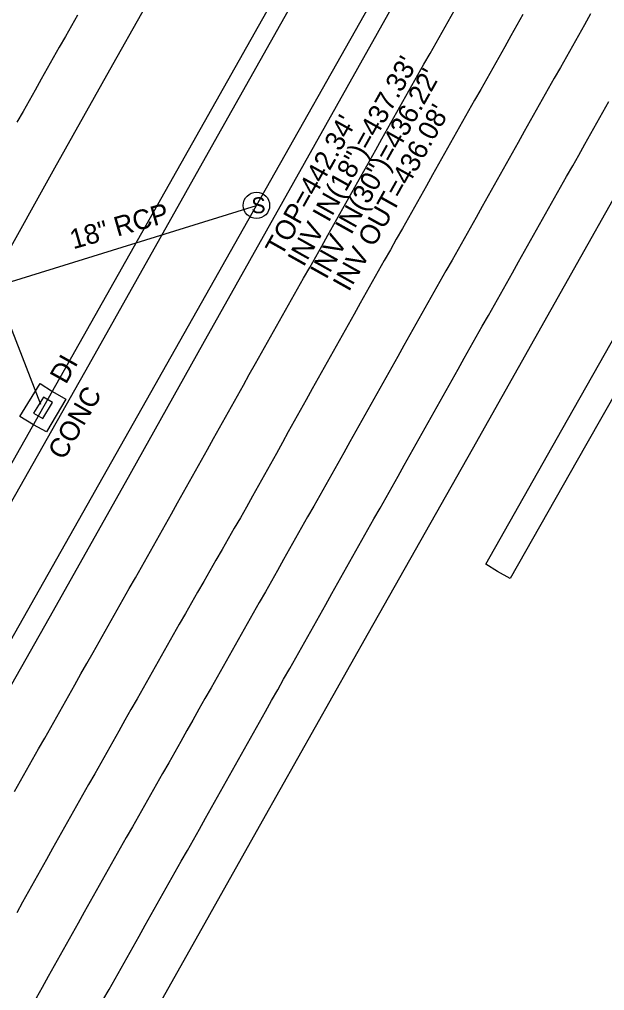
# Model space of a CAD drawing. Extents: x 2074109 to 2077820, y 741079 to 746031.
# Drawn here: x 2075216 to 2075335.2, y 742680.2 to 742877.9 of the extents above; entities that cross this region are included whole.
import ezdxf

# ---------------------------------------------------------------- set-up
doc = ezdxf.new("R2010")
doc.units = 0
for name, color, linetype in [('Exist Guardrail Cable Guide Rail', 7, 'Continuous'), ('Exist Horizontal Alignment', 7, 'Continuous'), ('Exist Roads EOP', 7, 'Continuous'), ('Exist Roads EOT', 7, 'Continuous'), ('Exist Structure Minor Drop Inlet', 7, 'Continuous'), ('Exist Structure Minor Drop Inlet Text', 7, 'Continuous'), ('Exist Structure Minor Paved Ditch or Gutter', 7, 'Continuous'), ('Exist Structure Minor Paved Ditch or Gutter Text', 7, 'Continuous'), ('Exist Structure Minor Pipes RCP 18 Inch', 7, 'Continuous'), ('Exist Structure Minor Pipes RCP 18 Inch Text', 7, 'Continuous'), ('Exist Structure Minor Pipes RCP 24 Inch Invert', 7, 'Continuous'), ('Exist Structure Minor Pipes RCP 30 Inch', 7, 'Continuous'), ('Exist Structure Minor Pipes RCP 30 Inch Invert', 7, 'Continuous'), ('Exist Structure Minor Storm Sewer Manhole CELL', 7, 'Continuous'), ('Exist Structure Minor Storm Sewer Manhole Text', 7, 'Continuous')]:
    doc.layers.add(name, color=color, linetype=linetype)

msp = doc.modelspace()

# ---------------------------------------------------------------- linework, layer by layer
at = {"layer": 'Exist Guardrail Cable Guide Rail'}
msp.add_line((2075230.21, 742807.65), (2075255.1, 742852.02), dxfattribs=at)
for points in [[(2075255.1, 742852.02), (2075298.94, 742929.85), (2075345.78, 743013.07), (2075384.51, 743080.82), (2075424.32, 743152.8), (2075460.45, 743220.68)], [(2075043.78, 742487.09), (2075058.56, 742508.52), (2075082.64, 742547.78), (2075110.14, 742595.62), (2075138.25, 742645.19), (2075162.9, 742688.2), (2075192.42, 742740.98), (2075230.21, 742807.65)]]:
    msp.add_lwpolyline(points, dxfattribs=at)
at = {"layer": 'Exist Horizontal Alignment'}
msp.add_line((2074886.11, 742205.34), (2075575.25, 743427.42), dxfattribs=at)
at = {"layer": 'Exist Roads EOP'}
for points in [[(2075082.27, 742583.2), (2075090.46, 742602.42), (2075097.51, 742619.27), (2075103.18, 742632.87), (2075107.04, 742641.29), (2075110.49, 742647.54), (2075117.02, 742659.24), (2075126.42, 742676.04), (2075137.8, 742696.19), (2075150.38, 742718.4), (2075162.39, 742739.69), (2075174.19, 742760.67), (2075186.87, 742783.1), (2075199.9, 742806.12), (2075211.88, 742827.44), (2075223.21, 742847.7), (2075235.01, 742868.73), (2075246.83, 742889.73)], [(2075297.48, 742890.45), (2075284.83, 742867.93), (2075269.65, 742840.85), (2075253.28, 742811.72), (2075237.58, 742783.58), (2075222.02, 742755.92), (2075207.65, 742730.63), (2075195.18, 742708.56), (2075181.14, 742683.69), (2075166.05, 742656.95), (2075153.79, 742635.53), (2075144.79, 742622.27), (2075137.94, 742612.64), (2075128.78, 742600.5), (2075119.38, 742587.81), (2075112.7, 742578.93), (2075100.64, 742561.46), (2075086.67, 742540.76)], [(2075349.99, 742864.53), (2075330.27, 742829.51), (2075308.21, 742790.39), (2075287.02, 742752.93), (2075265.47, 742714.71), (2075243.99, 742676.52)]]:
    msp.add_lwpolyline(points, dxfattribs=at)
at = {"layer": 'Exist Roads EOT'}
for points in [[(2075215.02, 742720.7), (2075216.25, 742722.88), (2075217.48, 742725.06), (2075218.71, 742727.24), (2075219.93, 742729.41), (2075221.16, 742731.59), (2075222.39, 742733.77), (2075223.62, 742735.94), (2075224.85, 742738.12), (2075226.08, 742740.3), (2075227.31, 742742.47), (2075228.54, 742744.65), (2075229.77, 742746.82), (2075231, 742749), (2075232.23, 742751.17), (2075233.46, 742753.35), (2075234.69, 742755.53), (2075235.92, 742757.7), (2075237.16, 742759.88), (2075238.39, 742762.05), (2075239.62, 742764.23), (2075240.85, 742766.41), (2075242.08, 742768.58), (2075243.31, 742770.76), (2075244.54, 742772.93), (2075245.77, 742775.11), (2075247, 742777.29), (2075248.22, 742779.47), (2075249.44, 742781.65), (2075250.65, 742783.83), (2075251.87, 742786.02), (2075253.09, 742788.2), (2075254.31, 742790.38), (2075255.53, 742792.57), (2075256.74, 742794.75), (2075257.96, 742796.93), (2075259.18, 742799.11), (2075260.4, 742801.3), (2075261.62, 742803.48), (2075262.83, 742805.66), (2075264.06, 742807.84), (2075265.29, 742810.02), (2075266.52, 742812.19), (2075267.75, 742814.37), (2075268.98, 742816.55), (2075270.2, 742818.73), (2075271.43, 742820.9), (2075272.66, 742823.08), (2075273.89, 742825.26), (2075275.12, 742827.43), (2075276.35, 742829.61), (2075277.57, 742831.79), (2075278.8, 742833.97), (2075280.03, 742836.15), (2075281.25, 742838.33), (2075282.47, 742840.51), (2075283.69, 742842.69), (2075284.92, 742844.87), (2075286.14, 742847.05), (2075287.36, 742849.23), (2075288.58, 742851.41), (2075289.81, 742853.59), (2075291.03, 742855.77), (2075292.25, 742857.95), (2075293.47, 742860.13), (2075294.7, 742862.31), (2075295.93, 742864.48), (2075297.16, 742866.66), (2075298.39, 742868.83), (2075299.62, 742871.01), (2075300.86, 742873.18), (2075302.09, 742875.36), (2075303.32, 742877.54), (2075304.55, 742879.71)], [(2075318.55, 742878.91), (2075317.32, 742876.74), (2075316.09, 742874.56), (2075314.86, 742872.38), (2075313.63, 742870.21), (2075312.4, 742868.03), (2075311.17, 742865.86), (2075309.94, 742863.68), (2075308.71, 742861.51), (2075307.48, 742859.33), (2075306.25, 742857.15), (2075305.02, 742854.97), (2075303.8, 742852.79), (2075302.58, 742850.61), (2075301.35, 742848.43), (2075300.13, 742846.26), (2075298.9, 742844.08), (2075297.67, 742841.9), (2075296.44, 742839.72), (2075295.22, 742837.55), (2075293.99, 742835.37), (2075292.76, 742833.19), (2075291.54, 742831.01), (2075290.31, 742828.83), (2075289.08, 742826.66), (2075287.85, 742824.48), (2075286.63, 742822.3), (2075285.4, 742820.13), (2075284.17, 742817.95), (2075282.94, 742815.77), (2075281.71, 742813.59), (2075280.5, 742811.41), (2075279.28, 742809.23), (2075278.06, 742807.04), (2075276.85, 742804.86), (2075275.63, 742802.68), (2075274.41, 742800.49), (2075273.2, 742798.31), (2075271.98, 742796.12), (2075270.76, 742793.94), (2075269.55, 742791.76), (2075268.33, 742789.57), (2075267.11, 742787.39), (2075265.9, 742785.2), (2075264.69, 742783.02), (2075263.47, 742780.83), (2075262.26, 742778.65), (2075261.02, 742776.48), (2075259.77, 742774.31), (2075258.53, 742772.14), (2075257.28, 742769.98), (2075256.03, 742767.81), (2075254.79, 742765.64), (2075253.54, 742763.48), (2075252.29, 742761.31), (2075251.05, 742759.14), (2075249.8, 742756.98), (2075248.56, 742754.81), (2075247.31, 742752.64), (2075246.08, 742750.47), (2075244.86, 742748.29), (2075243.64, 742746.1), (2075242.42, 742743.92), (2075241.19, 742741.75), (2075239.96, 742739.57), (2075238.73, 742737.39), (2075237.49, 742735.22), (2075236.26, 742733.04), (2075235.03, 742730.87), (2075233.8, 742728.69), (2075232.57, 742726.52), (2075231.34, 742724.34), (2075230.11, 742722.17), (2075228.88, 742719.99), (2075227.65, 742717.81), (2075226.42, 742715.64), (2075225.2, 742713.46), (2075223.97, 742711.28), (2075222.75, 742709.1), (2075221.53, 742706.91), (2075220.32, 742704.73), (2075219.1, 742702.55), (2075217.89, 742700.36), (2075216.67, 742698.18), (2075215.46, 742695.99)], [(2075227.84, 742878.78), (2075226.6, 742876.61), (2075225.37, 742874.44), (2075224.13, 742872.26), (2075222.9, 742870.09), (2075221.67, 742867.91), (2075220.44, 742865.74), (2075219.21, 742863.56), (2075217.98, 742861.38), (2075216.75, 742859.21), (2075215.52, 742857.03)], [(2075332.29, 742879.04), (2075331.06, 742876.86), (2075329.84, 742874.68), (2075328.61, 742872.5), (2075327.38, 742870.32), (2075326.16, 742868.15), (2075324.93, 742865.97), (2075323.7, 742863.79), (2075322.47, 742861.61), (2075321.25, 742859.44), (2075320.02, 742857.26), (2075318.79, 742855.08), (2075317.57, 742852.9), (2075316.34, 742850.72), (2075315.13, 742848.54), (2075313.92, 742846.35), (2075312.71, 742844.16), (2075311.49, 742841.98), (2075310.25, 742839.81), (2075309.02, 742837.63), (2075307.79, 742835.46), (2075306.56, 742833.28), (2075305.33, 742831.11), (2075304.1, 742828.93), (2075302.86, 742826.76), (2075301.63, 742824.58), (2075300.4, 742822.41), (2075299.17, 742820.23), (2075297.94, 742818.06), (2075296.71, 742815.88), (2075295.49, 742813.7), (2075294.27, 742811.51), (2075293.05, 742809.33), (2075291.84, 742807.15), (2075290.61, 742804.97), (2075289.39, 742802.79), (2075288.17, 742800.61), (2075286.94, 742798.43), (2075285.72, 742796.25), (2075284.5, 742794.07), (2075283.27, 742791.89), (2075282.05, 742789.71), (2075280.83, 742787.53), (2075279.61, 742785.35), (2075278.38, 742783.17), (2075277.16, 742780.99), (2075275.93, 742778.81), (2075274.7, 742776.63), (2075273.47, 742774.46), (2075272.24, 742772.28), (2075271.01, 742770.11), (2075269.78, 742767.93), (2075268.55, 742765.75), (2075267.32, 742763.58), (2075266.09, 742761.4), (2075264.86, 742759.22), (2075263.63, 742757.05), (2075262.4, 742754.87), (2075261.18, 742752.69), (2075259.95, 742750.52), (2075258.72, 742748.34), (2075257.49, 742746.16), (2075256.26, 742743.99), (2075255.03, 742741.81), (2075253.8, 742739.63), (2075252.57, 742737.46), (2075251.34, 742735.28), (2075250.11, 742733.11), (2075248.88, 742730.93), (2075247.64, 742728.76), (2075246.41, 742726.58), (2075245.18, 742724.41), (2075243.94, 742722.23), (2075242.71, 742720.06), (2075241.48, 742717.88), (2075240.25, 742715.71), (2075239.01, 742713.54), (2075237.78, 742711.36), (2075236.55, 742709.19), (2075235.32, 742707.01), (2075234.09, 742704.84), (2075232.86, 742702.66), (2075231.63, 742700.48), (2075230.41, 742698.3), (2075229.19, 742696.12), (2075227.97, 742693.93), (2075226.75, 742691.75), (2075225.53, 742689.57), (2075224.31, 742687.39), (2075223.09, 742685.21), (2075221.87, 742683.03), (2075220.65, 742680.84), (2075219.43, 742678.66)], [(2075233.03, 742678.23), (2075234.26, 742680.41), (2075235.49, 742682.59), (2075236.71, 742684.76), (2075237.94, 742686.94), (2075239.17, 742689.12), (2075240.39, 742691.3), (2075241.62, 742693.48), (2075242.85, 742695.65), (2075244.07, 742697.83), (2075245.3, 742700.01), (2075246.53, 742702.19), (2075247.75, 742704.37), (2075248.98, 742706.54), (2075250.21, 742708.72), (2075251.43, 742710.9), (2075252.66, 742713.08), (2075253.89, 742715.26), (2075255.11, 742717.44), (2075256.34, 742719.61), (2075257.57, 742721.79), (2075258.79, 742723.97), (2075260.02, 742726.15), (2075261.24, 742728.33), (2075262.47, 742730.5), (2075263.7, 742732.68), (2075264.92, 742734.86), (2075266.15, 742737.04), (2075267.37, 742739.22), (2075268.6, 742741.4), (2075269.82, 742743.58), (2075271.05, 742745.76), (2075272.27, 742747.93), (2075273.5, 742750.11), (2075274.72, 742752.29), (2075275.95, 742754.47), (2075277.17, 742756.65), (2075278.4, 742758.83), (2075279.62, 742761.01), (2075280.85, 742763.19), (2075282.08, 742765.36), (2075283.3, 742767.54), (2075284.53, 742769.72), (2075285.76, 742771.9), (2075286.98, 742774.08), (2075288.21, 742776.25), (2075289.44, 742778.43), (2075290.67, 742780.61), (2075291.89, 742782.79), (2075293.12, 742784.96), (2075294.35, 742787.14), (2075295.57, 742789.32), (2075296.8, 742791.5), (2075298.03, 742793.68), (2075299.25, 742795.86), (2075300.48, 742798.04), (2075301.7, 742800.21), (2075302.93, 742802.39), (2075304.15, 742804.57), (2075305.37, 742806.75), (2075306.6, 742808.93), (2075307.82, 742811.11), (2075309.05, 742813.29), (2075310.27, 742815.47), (2075311.5, 742817.65), (2075312.72, 742819.83), (2075313.95, 742822), (2075315.18, 742824.18), (2075316.4, 742826.36), (2075317.63, 742828.54), (2075318.86, 742830.72), (2075320.08, 742832.89), (2075321.31, 742835.07), (2075322.54, 742837.25), (2075323.76, 742839.43), (2075324.99, 742841.61), (2075326.22, 742843.78), (2075327.44, 742845.96), (2075328.67, 742848.14), (2075329.9, 742850.32), (2075331.12, 742852.5), (2075332.35, 742854.67), (2075333.58, 742856.85), (2075334.81, 742859.03), (2075336.03, 742861.21)]]:
    msp.add_lwpolyline(points, dxfattribs=at)
at = {"layer": 'Exist Structure Minor Drop Inlet'}
msp.add_lwpolyline([(2075220.89, 742801.04), (2075218.9, 742797.78), (2075220.77, 742796.65), (2075222.75, 742799.9)], close=True, dxfattribs=at)
at = {"layer": 'Exist Structure Minor Paved Ditch or Gutter'}
for points in [[(2075381.77, 742879.44), (2075355.36, 742833.4), (2075331.29, 742791.11), (2075315.93, 742764.1), (2075313.38, 742765.52), (2075310.97, 742766.98), (2075326.43, 742794.39), (2075350.27, 742836.4), (2075376.88, 742883)], [(2075220.23, 742803.78), (2075222.73, 742802.18), (2075225.49, 742800.61), (2075221.53, 742793.94), (2075218.87, 742795.39), (2075216.1, 742797.05), (2075220.23, 742803.78)]]:
    msp.add_lwpolyline(points, dxfattribs=at)
at = {"layer": 'Exist Structure Minor Pipes RCP 18 Inch'}
for p, q in [((2075212.46, 742823.93), (2075264.27, 742840.07)), ((2075211.47, 742822.3), (2075220.31, 742799.59))]:
    msp.add_line(p, q, dxfattribs=at)
at = {"layer": 'Exist Structure Minor Pipes RCP 30 Inch'}
for p, q in [((2075264.27, 742840.07), (2075435.52, 743142.56)), ((2074933.64, 742254.78), (2075264.27, 742840.07))]:
    msp.add_line(p, q, dxfattribs=at)
at = {"layer": 'Exist Structure Minor Storm Sewer Manhole CELL'}
msp.add_circle((2075264.27, 742840.07), 2.69, dxfattribs=at)

# ---------------------------------------------------------------- texts
at = {"layer": 'Exist Structure Minor Drop Inlet Text'}
msp.add_text('DI', height=4, rotation=60.7411, dxfattribs=at).set_placement((2075225.49, 742803.47))
at = {"layer": 'Exist Structure Minor Paved Ditch or Gutter Text'}
msp.add_text('CONC', height=4, rotation=60.1413, dxfattribs=at).set_placement((2075225.07, 742788.01))
at = {"layer": 'Exist Structure Minor Pipes RCP 18 Inch Text'}
msp.add_text('18" RCP', height=4, rotation=15.9959, dxfattribs=at).set_placement((2075226.97, 742831.11))
at = {"layer": 'Exist Structure Minor Pipes RCP 24 Inch Invert'}
msp.add_text('INV IN(18")=437.33\'', height=4, rotation=60.7411, dxfattribs=at).set_placement((2075273.89, 742827.37))
at = {"layer": 'Exist Structure Minor Pipes RCP 30 Inch Invert'}
for s, p in [('INV IN(30")=436.22\'', (2075278.49, 742824.83)), ("INV OUT=436.08'", (2075283.1, 742822.32))]:
    msp.add_text(s, height=4, rotation=60.7411, dxfattribs=at).set_placement(p)
at = {"layer": 'Exist Structure Minor Storm Sewer Manhole CELL'}
msp.add_text('S', height=3.25, dxfattribs=at).set_placement((2075263.24, 742838.46))
at = {"layer": 'Exist Structure Minor Storm Sewer Manhole Text'}
msp.add_text("TOP=442.34'", height=4, rotation=60.7411, dxfattribs=at).set_placement((2075269.37, 742829.48))

doc.saveas('drawing.dxf')
